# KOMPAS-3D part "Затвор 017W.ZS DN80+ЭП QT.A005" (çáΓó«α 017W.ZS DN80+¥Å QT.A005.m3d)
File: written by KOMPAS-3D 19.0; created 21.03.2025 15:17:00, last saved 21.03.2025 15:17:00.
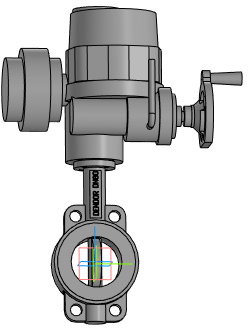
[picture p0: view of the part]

Document properties: Полное имя файла: Затвор 017W.ZS DN80+ЭП QT.A005.a3d

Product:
- Part/product: Затвор 017W.ZS DN80+ЭП QT.A005
    Масса: 40.8865

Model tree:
1. Операция без истории:1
